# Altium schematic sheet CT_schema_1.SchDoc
size 655 x 560 mm
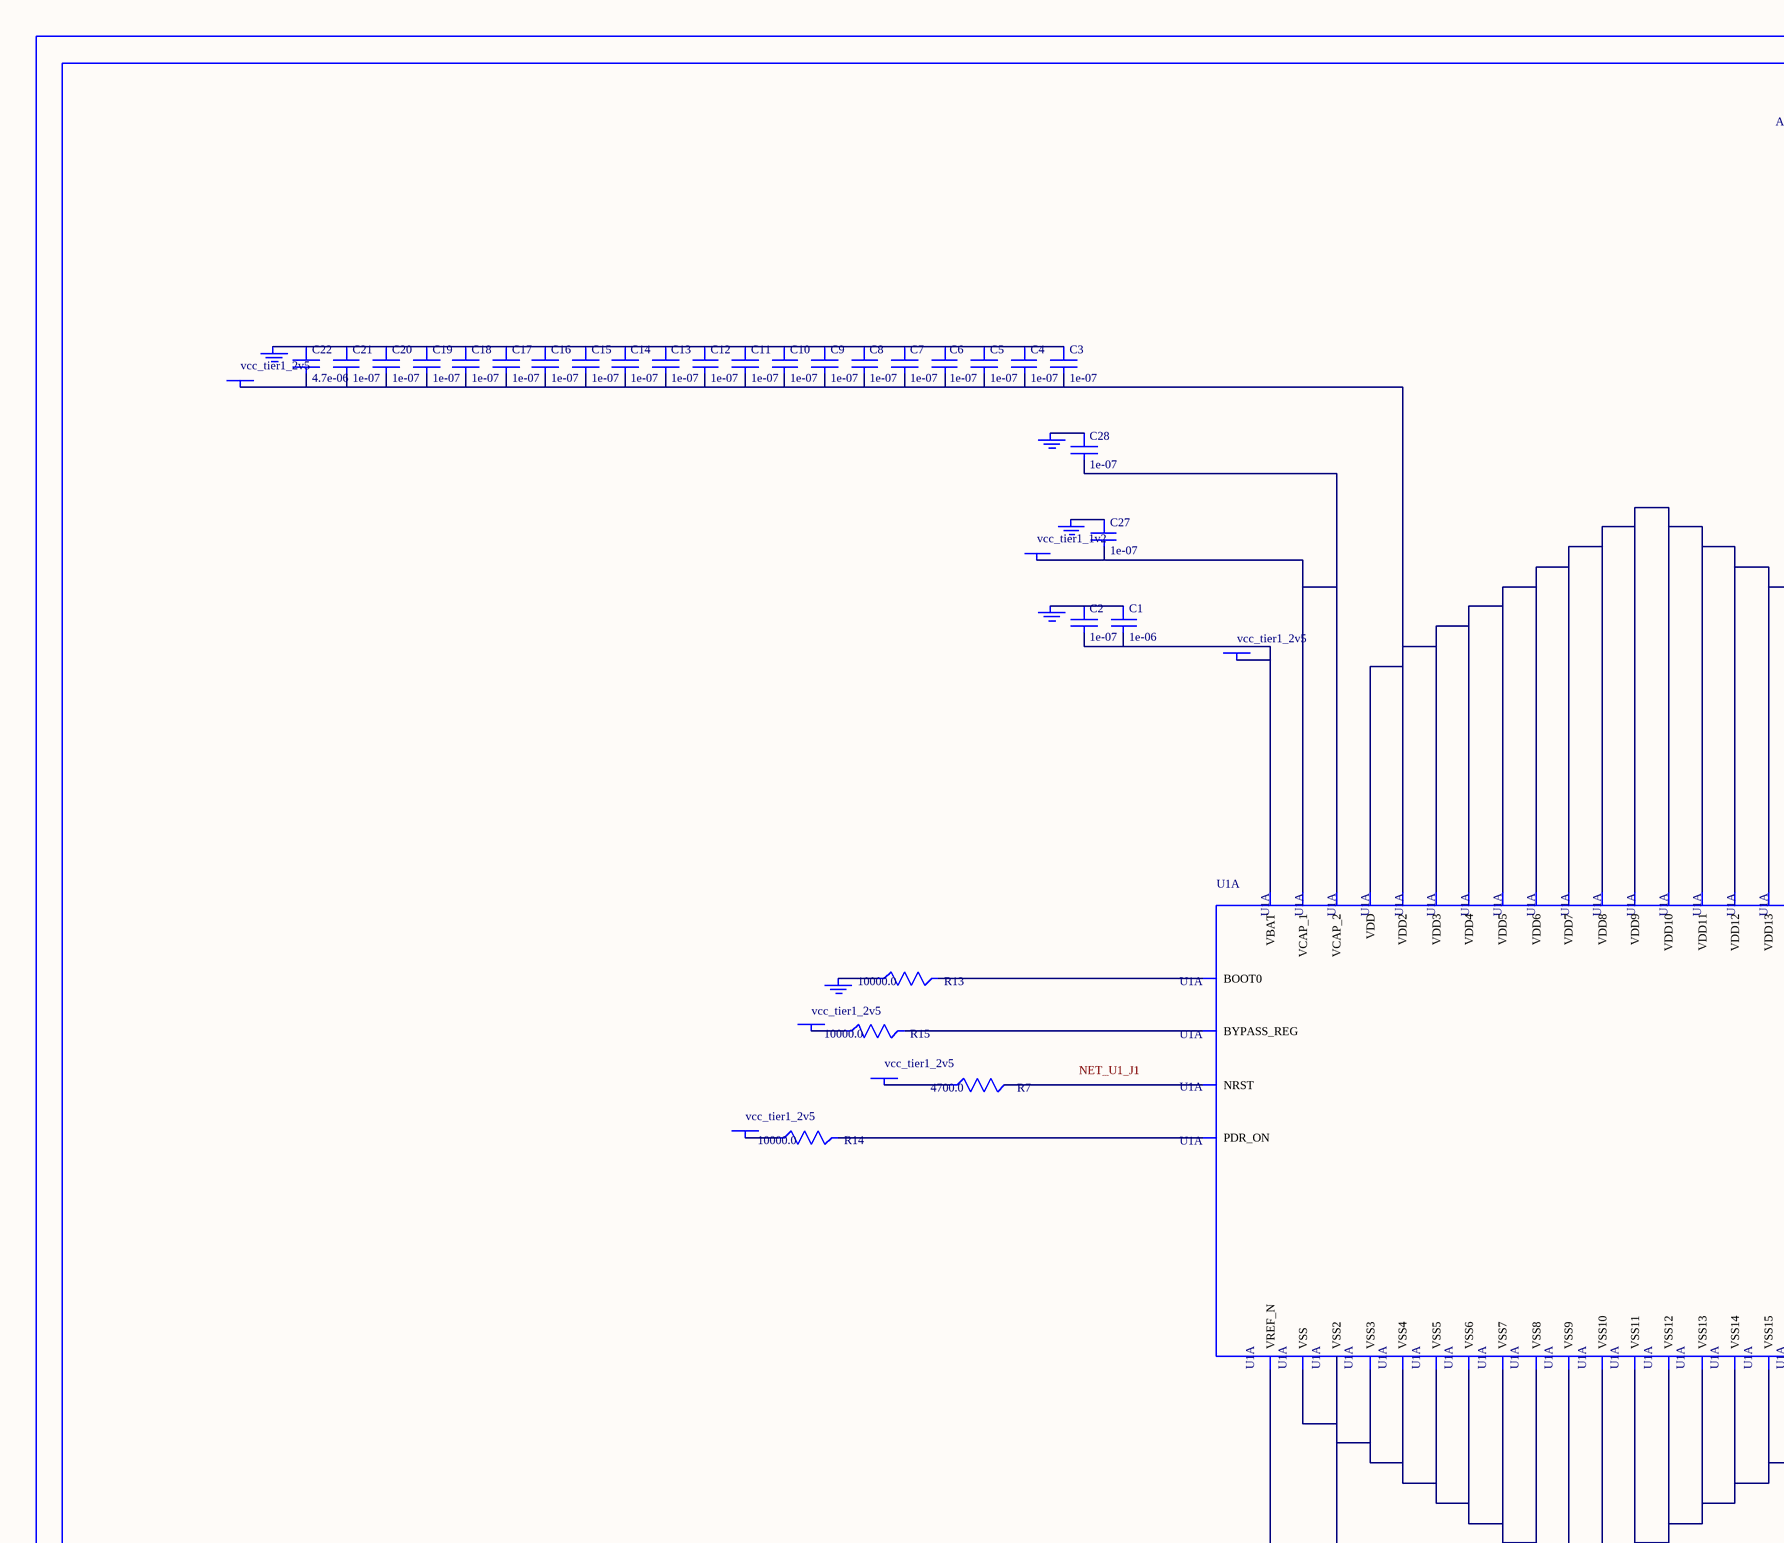
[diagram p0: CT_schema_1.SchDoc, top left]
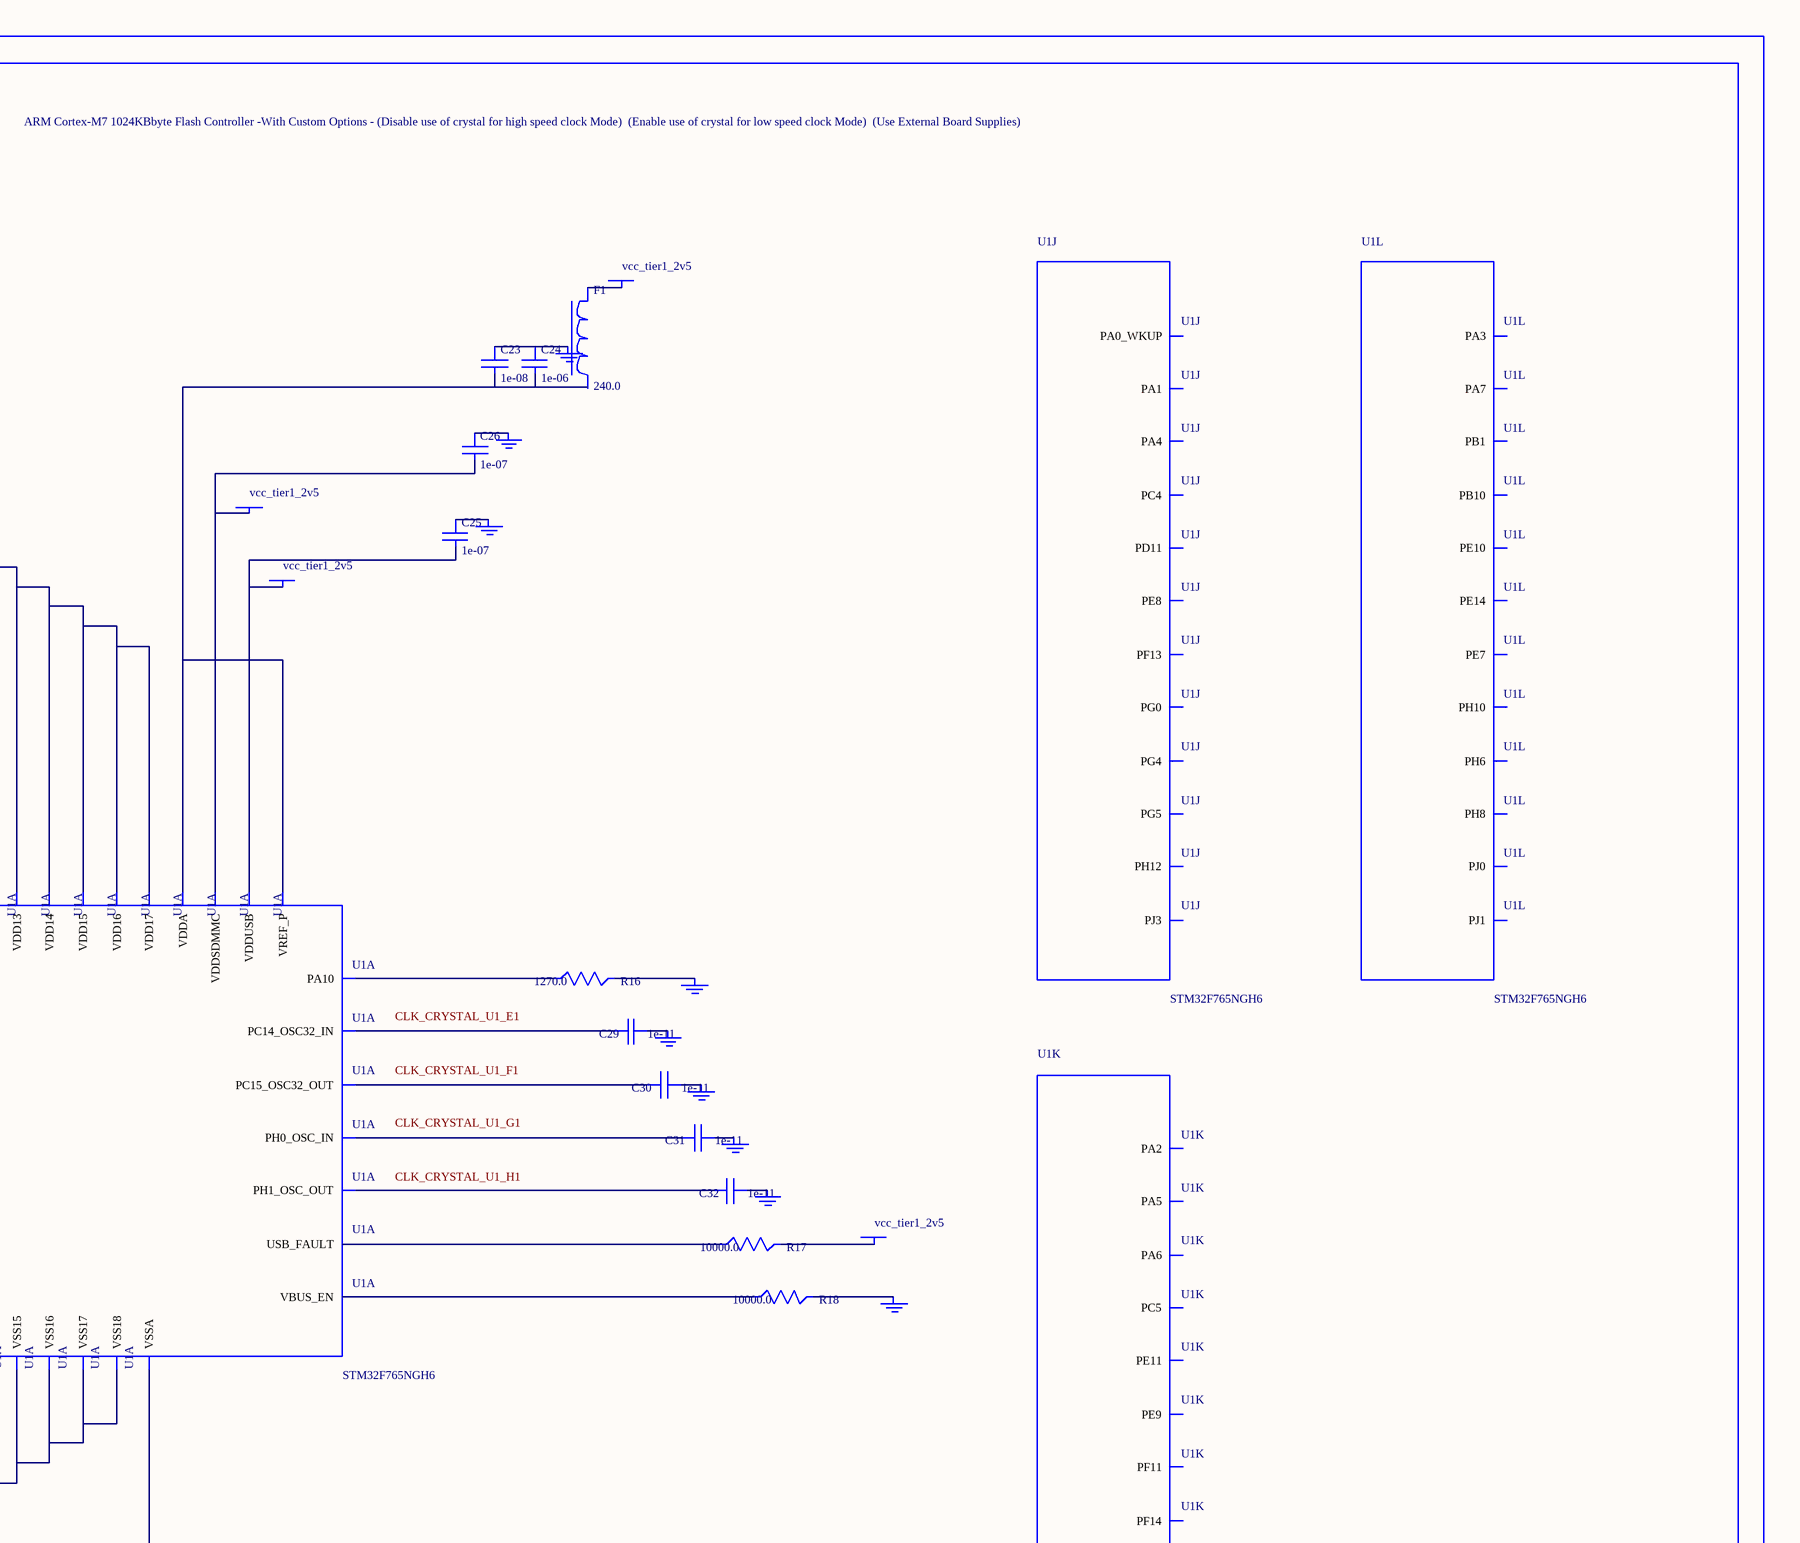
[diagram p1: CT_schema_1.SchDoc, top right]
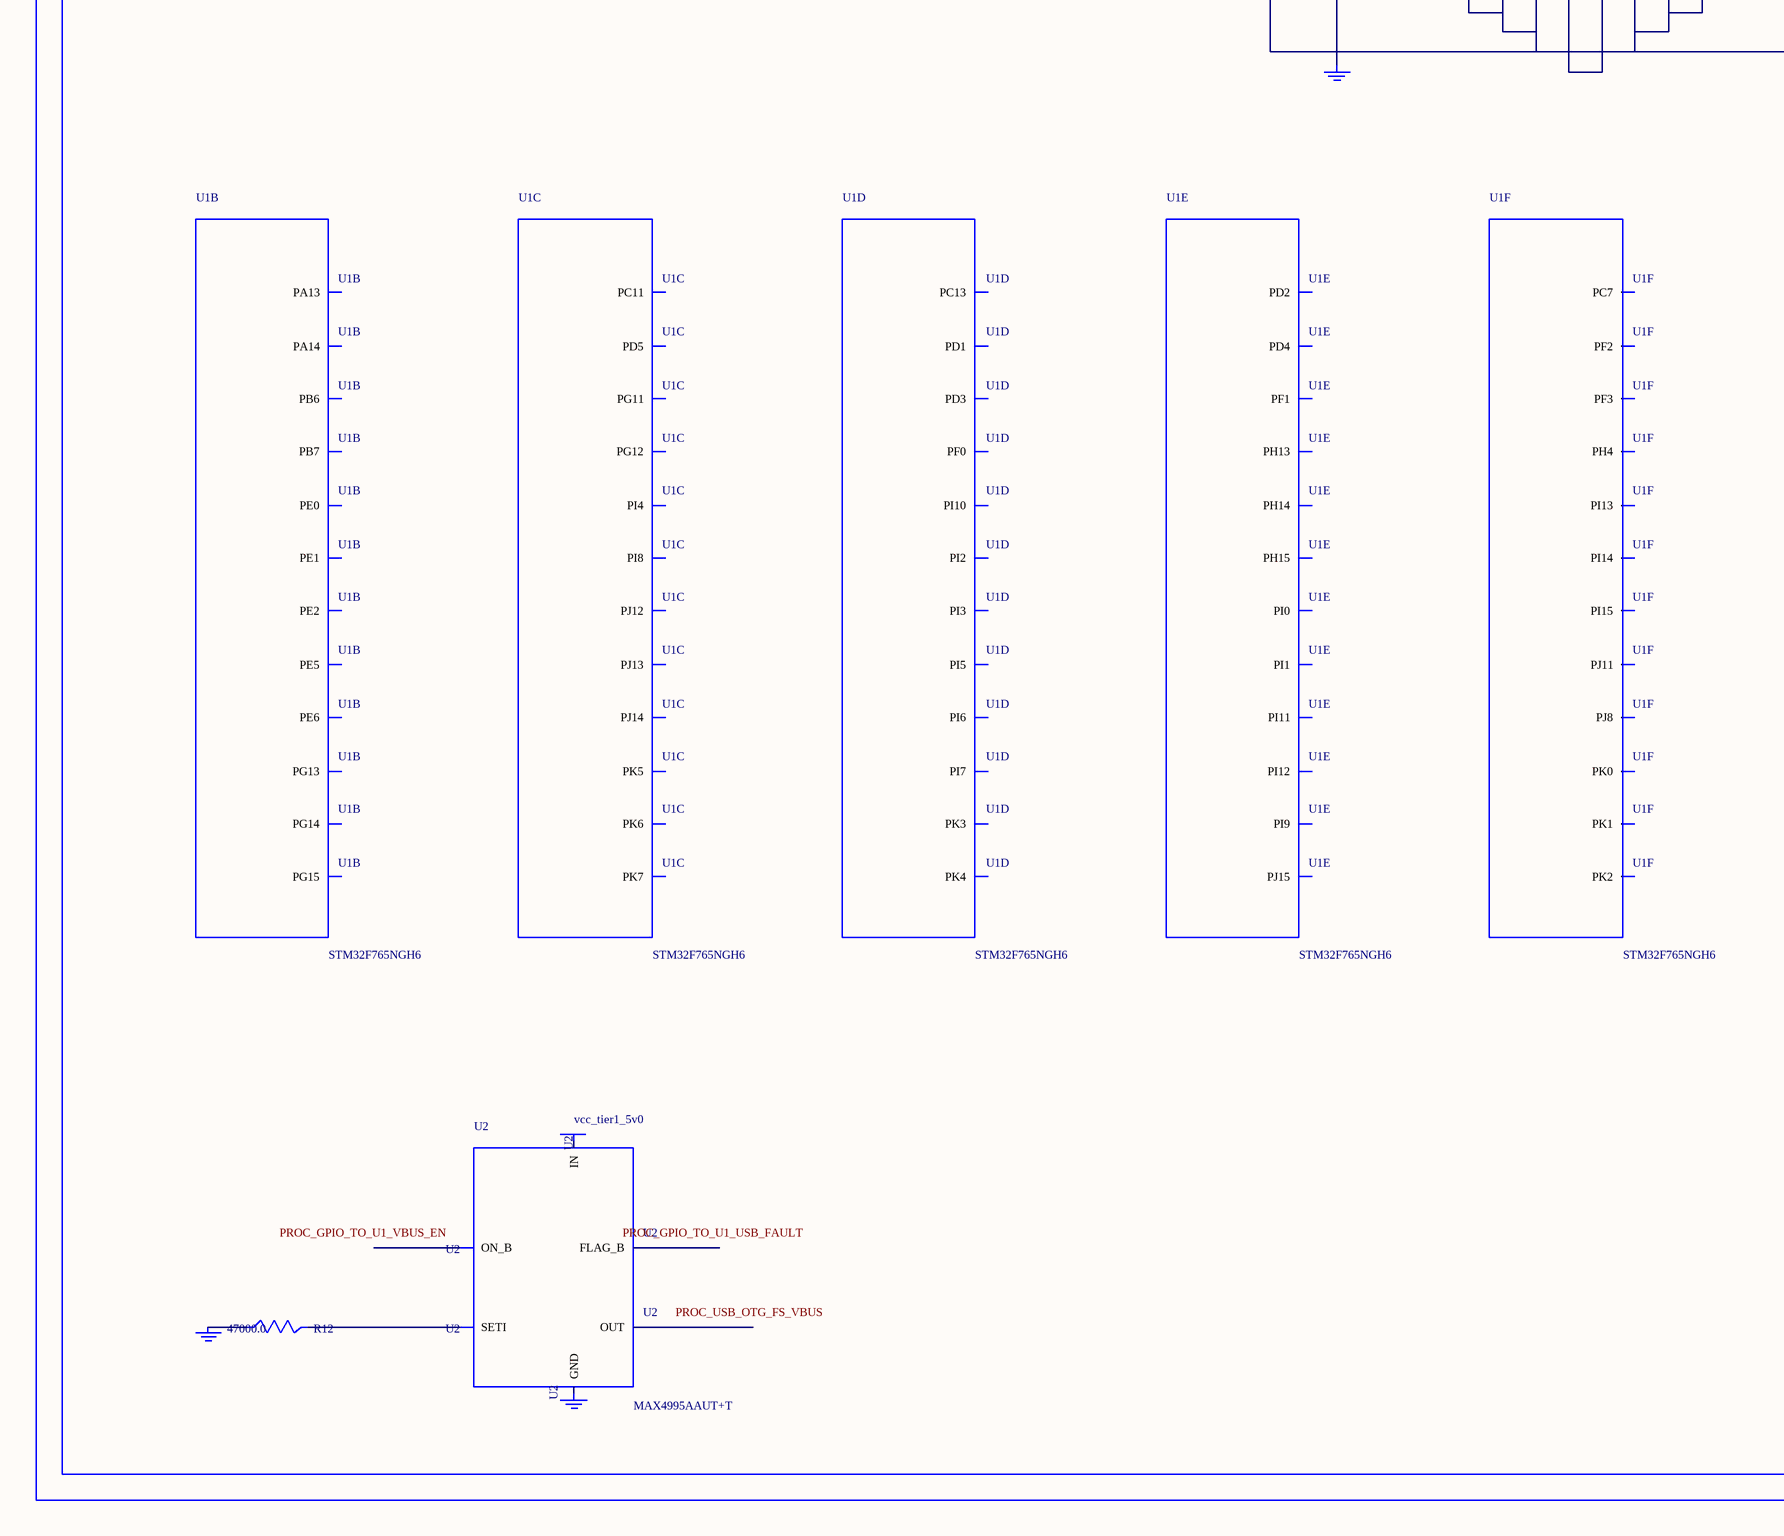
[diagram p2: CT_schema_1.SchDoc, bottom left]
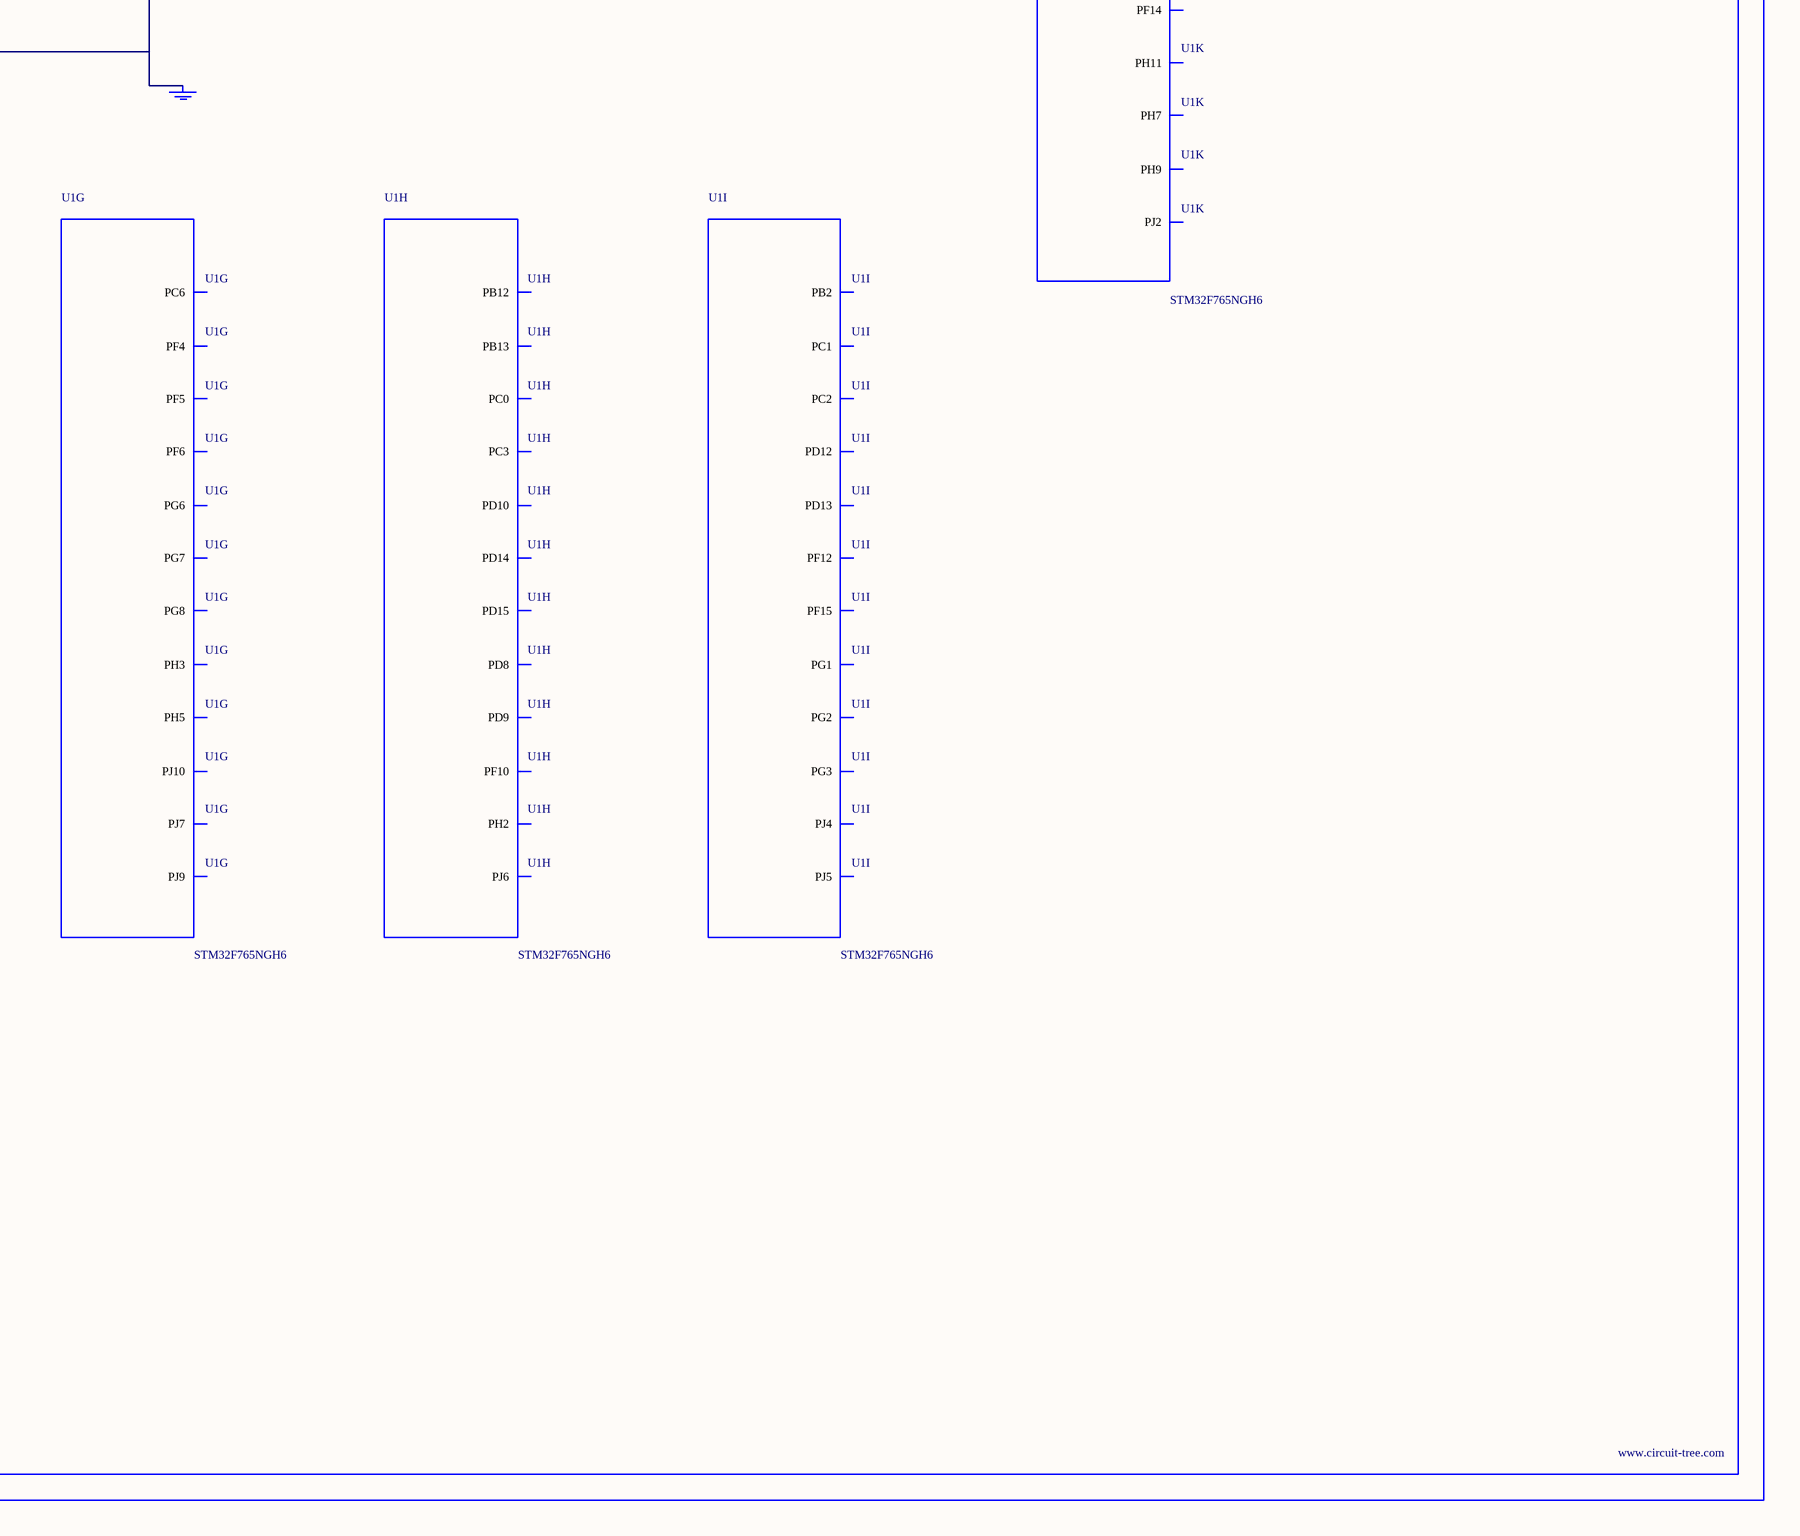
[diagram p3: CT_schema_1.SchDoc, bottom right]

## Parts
BORDER0  (no value)
C1  1e-06  [C0603]
C2  1e-07  [C0603]
C3  1e-07  [C0603]
C4  1e-07  [C0603]
C5  1e-07  [C0603]
C6  1e-07  [C0603]
C7  1e-07  [C0603]
C8  1e-07  [C0603]
C9  1e-07  [C0603]
C10  1e-07  [C0603]
C11  1e-07  [C0603]
C12  1e-07  [C0603]
C13  1e-07  [C0603]
C14  1e-07  [C0603]
C15  1e-07  [C0603]
C16  1e-07  [C0603]
C17  1e-07  [C0603]
C18  1e-07  [C0603]
C19  1e-07  [C0603]
C20  1e-07  [C0603]
C21  1e-07  [C0603]
C22  4.7e-06  [C0603]
C23  1e-08  [C0603]
C24  1e-06  [C0603]
C25  1e-07  [C0603]
C26  1e-07  [C0603]
C27  1e-07  [C0603]
C28  1e-07  [C0603]
C29  1e-11  [C0402]
C30  1e-11  [C0402]
C31  1e-11  [C0402]
C32  1e-11  [C0402]
F1  240.0  [L0603]
GND_INSTANCE_0_0  (no value)
GND_INSTANCE_0_1  (no value)
GND_INSTANCE_0_2  (no value)
GND_INSTANCE_0_3  (no value)
GND_INSTANCE_0_4  (no value)
GND_INSTANCE_0_5  (no value)
GND_INSTANCE_0_6  (no value)
GND_INSTANCE_0_7  (no value)
GND_INSTANCE_0_8  (no value)
GND_INSTANCE_0_9  (no value)
GND_INSTANCE_0_10  (no value)
GND_INSTANCE_0_11  (no value)
GND_INSTANCE_0_12  (no value)
GND_INSTANCE_0_13  (no value)
GND_INSTANCE_0_14  (no value)
GND_INSTANCE_0_15  (no value)
GND_INSTANCE_0_16  (no value)
GND_INSTANCE_0_17  (no value)
POWER_INSTANCE_0_0  vcc_tier1_2v5
POWER_INSTANCE_0_1  vcc_tier1_2v5
POWER_INSTANCE_0_2  vcc_tier1_2v5
POWER_INSTANCE_0_3  vcc_tier1_2v5
POWER_INSTANCE_0_4  vcc_tier1_2v5
POWER_INSTANCE_0_5  vcc_tier1_2v5
POWER_INSTANCE_0_6  vcc_tier1_2v5
POWER_INSTANCE_0_7  vcc_tier1_1v2
POWER_INSTANCE_0_8  vcc_tier1_2v5
POWER_INSTANCE_0_9  vcc_tier1_2v5
POWER_INSTANCE_0_10  vcc_tier1_5v0
R7  4700.0  [R0603]
R12  47000.0  [R0603]
R13  10000.0  [R0603]
R14  10000.0  [R0603]
R15  10000.0  [R0603]
R16  1270.0  [R0603]
R17  10000.0  [R0603]
R18  10000.0  [R0603]
U1  STM32F765NGH6  [TFBGA216]  (parts A,B,C,D,E,F,G,H,I,J,K,L of 18)
U2  MAX4995AAUT+T  [SOT-23-6]

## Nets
NetC1_1: C1.1 C2.1 GND_INSTANCE_0_0.0(GND)
NetC1_2: C1.2 C2.2 POWER_INSTANCE_0_0.0(PWR) U1.C1(VBAT)
NetC3_1: C3.1 C4.1 C5.1 C6.1 C7.1 C8.1 C9.1 C10.1 C11.1 C12.1 C13.1 C14.1 C15.1 C16.1 C17.1 C18.1 C19.1 C20.1 C21.1 C22.1 GND_INSTANCE_0_2.0(GND)
NetC3_2: C3.2 C4.2 C5.2 C6.2 C7.2 C8.2 C9.2 C10.2 C11.2 C12.2 C13.2 C14.2 C15.2 C16.2 C17.2 C18.2 C19.2 C20.2 C21.2 C22.2 POWER_INSTANCE_0_2.0(PWR) U1.E7(VDD2) U1.E8(VDD3) U1.E10(VDD) U1.F4(VDD5) U1.F5(VDD6) U1.F11(VDD4) U1.G5(VDD7) U1.H5(VDD9) U1.H11(VDD8) U1.J5(VDD11) U1.J11(VDD10) U1.K5(VDD13) U1.K11(VDD12) U1.L7(VDD15) U1.L8(VDD16) U1.L9(VDD17) U1.L10(VDD14)
NetC23_1: C23.1 C24.1 GND_INSTANCE_0_1.0(GND)
NetC23_2: C23.2 C24.2 U1.P1(VREF_P) U1.R1(VDDA)
NetC25_1: C25.1 GND_INSTANCE_0_4.0(GND)
NetC25_2: C25.2 POWER_INSTANCE_0_4.0(PWR) U1.G11(VDDUSB)
NetC26_1: C26.1 GND_INSTANCE_0_5.0(GND)
NetC26_2: C26.2 POWER_INSTANCE_0_5.0(PWR) U1.E9(VDDSDMMC)
NetC27_1: C27.1 GND_INSTANCE_0_6.0(GND)
NetC27_2: C27.2 C28.2 POWER_INSTANCE_0_7.0(PWR) U1.E11(VCAP_2) U1.L11(VCAP_1)
NetC28_1: C28.1 GND_INSTANCE_0_7.0(GND)
NetC29_1: C29.1 GND_INSTANCE_0_8.0(GND)
NetC29_2: C29.2 U1.E1(PC14_OSC32_IN)
NetC30_1: C30.1 GND_INSTANCE_0_9.0(GND)
NetC30_2: C30.2 U1.F1(PC15_OSC32_OUT)
NetC31_1: C31.1 GND_INSTANCE_0_10.0(GND)
NetC31_2: C31.2 U1.G1(PH0_OSC_IN)
NetC32_1: C32.1 GND_INSTANCE_0_11.0(GND)
NetC32_2: C32.2 U1.H1(PH1_OSC_OUT)
NetF1_1: F1.1 POWER_INSTANCE_0_1.0(PWR)
NetGND_INSTANCE_0_3_0: GND_INSTANCE_0_3.0(GND) R13.1
NetGND_INSTANCE_0_12_0: GND_INSTANCE_0_12.0(GND) R16.2
NetGND_INSTANCE_0_13_0: GND_INSTANCE_0_13.0(GND) R18.2
NetGND_INSTANCE_0_14_0: GND_INSTANCE_0_14.0(GND) GND_INSTANCE_0_15.0(GND) U1.F2(VSS2) U1.F6(VSS3) U1.F7(VSS4) U1.F8(VSS5) U1.F9(VSS6) U1.F10(VSS) U1.G6(VSS8) U1.G10(VSS7) U1.H6(VSS10) U1.H10(VSS9) U1.J6(VSS12) U1.J10(VSS11) U1.K6(VSS14) U1.K7(VSS15) U1.K8(VSS16) U1.K9(VSS17) U1.K10(VSS13) U1.L6(VSS18) U1.M1(VSSA) U1.N1(VREF_N)
NetGND_INSTANCE_0_16_0: GND_INSTANCE_0_16.0(GND) R12.1
NetPOWER_INSTANCE_0_3_0: POWER_INSTANCE_0_3.0(PWR) R14.1
NetPOWER_INSTANCE_0_6_0: POWER_INSTANCE_0_6.0(PWR) R15.1
NetPOWER_INSTANCE_0_8_0: POWER_INSTANCE_0_8.0(PWR) R17.2
NetPOWER_INSTANCE_0_9_0: POWER_INSTANCE_0_9.0(PWR) R7.1
NetR7_2: R7.2 U1.J1(NRST)
NetR12_2: R12.2 U2.3(SETI)
NetR13_2: R13.2 U1.E6(BOOT0)
NetR14_2: R14.2 U1.E5(PDR_ON)
NetR15_2: R15.2 U1.L5(BYPASS_REG)
NetR16_1: R16.1 U1.D15(PA10)
NetR17_1: R17.1 U1.A2(USB_FAULT)
NetR18_1: R18.1 U1.A1(VBUS_EN)

Not connected (* = marked no-connect by the designer): F1 2; GND_INSTANCE_0_17 0(GND); POWER_INSTANCE_0_10 0(PWR); U1 A3(PE2) A4(PG14) A5(PE1) A6(PE0) A14(PA14) A15(PA13) B1(PE5) B2(PE6) B3(PG13) B5(PB7) B6(PB6) B7(PG15) B8(PG11) B9(PJ13) B10(PJ12) B13(PC11) C2(PI8) C3(PI4) C4(PK7) C5(PK6) C6(PK5) C7(PG12) C9(PJ14) C10(PD5) C11(PD3) C12(PD1) C13(PI3) C14(PI2) D1(PC13) D2(PF0) D3(PI5) D4(PI7) D5(PI10) D6(PI6) D7(PK4) D8(PK3) D10(PJ15) D11(PD4) D12(PD2) D13(PH15) D14(PI1) E2(PF1) E3(PI12) E4(PI9) E12(PH13) E13(PH14) E14(PI0) F3(PI11) F12(PK1) F13(PK2) G2(PF2) G3(PI13) G4(PI15) G12(PJ11) G13(PK0) G15(PC7) H2(PF3) H3(PI14) H4(PH4) H12(PJ8) H13(PJ10) H14(PG8) H15(PC6) J2(PF4) J3(PH5) J4(PH3) J12(PJ7) J13(PJ9) J14(PG7) J15(PG6) K2(PF6) K3(PF5) K4(PH2) K12(PJ6) K13(PD15) K14(PB13) K15(PD10) L1(PF10) L4(PC3) L12(PD14) L13(PB12) L14(PD9) L15(PD8) M2(PC0) M3(PC1) M4(PC2) M5(PB2) M6(PF12) M7(PG1) M8(PF15) M9(PJ4) M10(PD12) M11(PD13) M12(PG3) M13(PG2) M14(PJ5) M15(PH12) N2(PA1) N3(PA0_WKUP) N4(PA4) N5(PC4) N6(PF13) N7(PG0) N8(PJ3) N9(PE8) N10(PD11) N11(PG5) N12(PG4) N13(PH7) N14(PH9) N15(PH11) P2(PA2) P3(PA6) P4(PA5) P5(PC5) P6(PF14) P7(PJ2) P8(PF11) P9(PE9) P10(PE11) P11(PE14) P12(PB10) P13(PH6) P14(PH8) P15(PH10) R2(PA3) R3(PA7) R4(PB1) R6(PJ0) R7(PJ1) R8(PE7) R9(PE10); U2 1(OUT) 2(GND) 4(ON_B) 5(IN) 6(FLAG_B)

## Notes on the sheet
- Labels drawn without touching a wire or pin: CLK_CRYSTAL_U1_E1, CLK_CRYSTAL_U1_F1, CLK_CRYSTAL_U1_G1, CLK_CRYSTAL_U1_H1, NET_U1_J1, PROC_GPIO_TO_U1_USB_FAULT, PROC_GPIO_TO_U1_VBUS_EN, PROC_USB_OTG_FS_VBUS

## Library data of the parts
BORDER0 = BORDER_PAGE0
C1 C24 = C0603C105K3RACTU
C2-C21 C25-C28 = 06035C104K4Z2A
C22 = GRM188R6YA475KE15D
C23 = 06035C103K4Z2A
C29-C32 = C0402C100K3GACTU
F1 = Z0603C241ASMST
GND_INSTANCE_0_0-GND_INSTANCE_0_17 = GND
POWER_INSTANCE_0_0-POWER_INSTANCE_0_10 = PWR
R7 = RC0603JR-074K7L
R12 = RC0603JR-0747KL
R13-R15 R17 R18 = RC0603JR-0710KL
R16 = RC0603FR-071K27L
